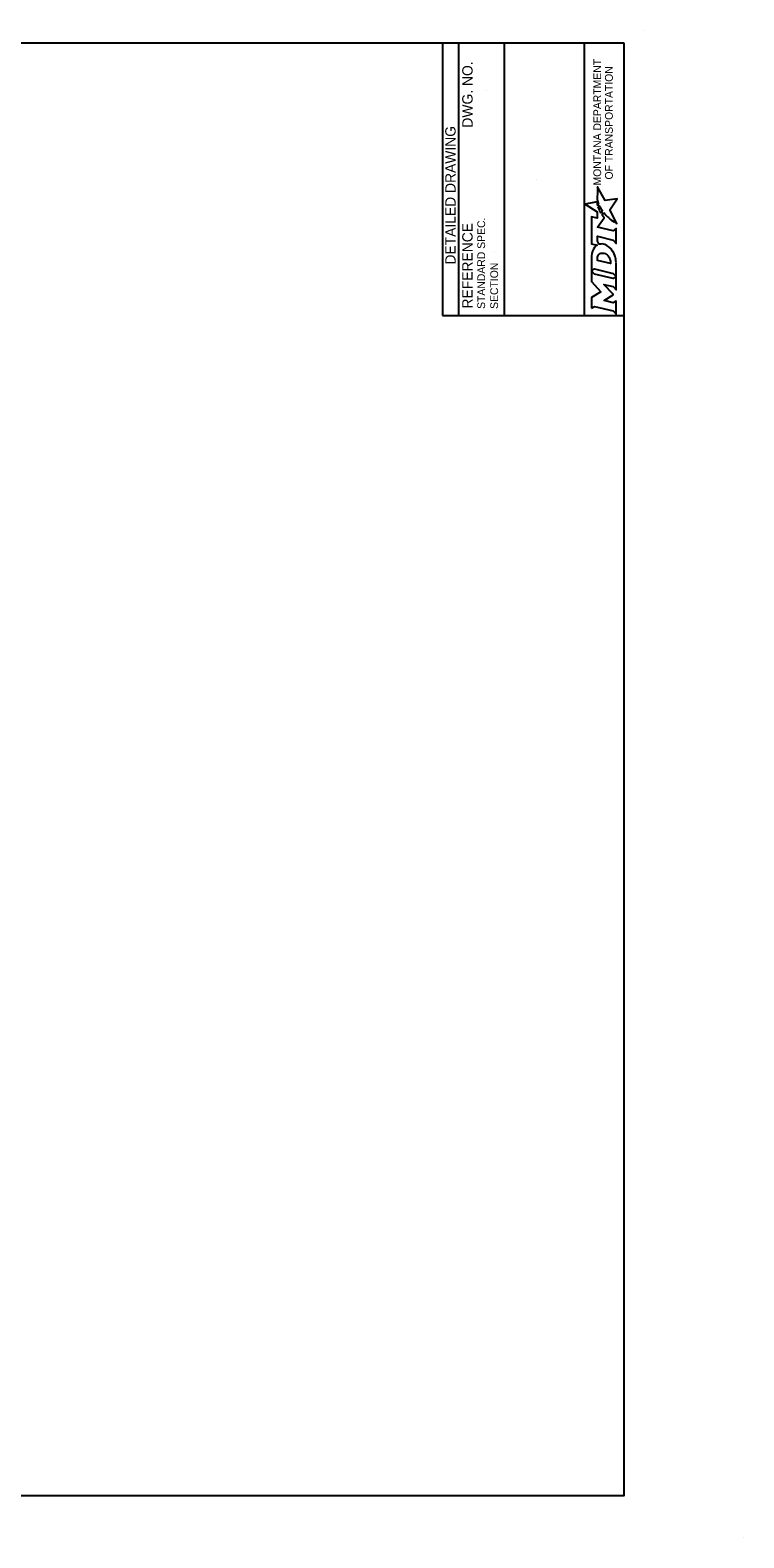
# Model space of a CAD drawing. Extents: x 49991.4 to 50048.3, y 49987.6 to 50018.3.
# Drawn here: x 50004.04 to 50009.54, y 49999.74 to 50011.36 of the extents above; entities that cross this region are included whole.
import ezdxf

# ---------------------------------------------------------------- set-up
doc = ezdxf.new("R2010")
doc.units = 0
doc.layers.add('Level 1', color=7, linetype='Continuous')
doc.layers.add('Level 3', color=7, linetype='Continuous')

msp = doc.modelspace()

# ---------------------------------------------------------------- linework, layer by layer
at = {"layer": 'Level 1'}
for p, q in [((50008.765, 50011.363), (50008.765, 50011.363)), ((50009.537, 49999.736), (50009.537, 49999.736))]:
    msp.add_line(p, q, dxfattribs=at)
msp.add_lwpolyline([(50008.615, 50011.263), (50000.336, 50011.263), (50000.336, 50000.062), (50008.615, 50000.062)], close=True, dxfattribs=at)
at = {"layer": 'Level 3'}
for p, q in [((50007.215, 50011.263), (50007.215, 50009.163)), ((50007.34, 50011.263), (50007.34, 50009.163)), ((50007.69, 50011.263), (50007.69, 50009.163)), ((50008.308, 50011.263), (50008.308, 50009.163)), ((50007.555, 50010.899), (50007.555, 50010.899)), ((50007.939, 50010.213), (50007.939, 50010.213)), ((50007.614, 50009.657), (50007.614, 50009.657)), ((50007.215, 50009.163), (50008.615, 50009.163))]:
    msp.add_line(p, q, dxfattribs=at)
for points in [[(50008.514, 50009.9), (50008.538, 50009.885), (50008.546, 50009.88), (50008.554, 50009.875), (50008.559, 50009.872), (50008.505, 50009.978), (50008.561, 50010.061), (50008.468, 50010.048), (50008.409, 50010.155), (50008.409, 50010.106), (50008.408, 50010.076), (50008.408, 50010.055), (50008.409, 50010.048), (50008.411, 50010.043), (50008.413, 50010.035), (50008.417, 50010.025)], [(50008.417, 50010.025), (50008.411, 50010.014), (50008.409, 50010.026), (50008.407, 50010.038), (50008.316, 50010.02), (50008.408, 50009.961), (50008.408, 50009.914), (50008.364, 50009.924), (50008.364, 50009.715), (50008.407, 50009.705), (50008.398, 50009.699)], [(50008.445, 50009.974), (50008.446, 50009.972), (50008.437, 50009.954), (50008.431, 50009.964), (50008.429, 50009.968), (50008.425, 50009.977), (50008.422, 50009.982), (50008.419, 50009.99), (50008.416, 50009.998), (50008.424, 50010.009), (50008.426, 50010.005), (50008.428, 50010.001), (50008.431, 50009.997), (50008.434, 50009.992), (50008.435, 50009.99), (50008.436, 50009.987), (50008.438, 50009.985), (50008.439, 50009.982), (50008.441, 50009.98), (50008.443, 50009.977), (50008.445, 50009.974)], [(50008.423, 50009.711), (50008.41, 50009.736), (50008.41, 50009.773), (50008.531, 50009.744), (50008.553, 50009.717), (50008.553, 50009.833), (50008.531, 50009.816), (50008.41, 50009.844), (50008.462, 50009.915), (50008.447, 50009.937), (50008.458, 50009.956)], [(50008.498, 50009.914), (50008.498, 50009.914)], [(50008.451, 50009.644), (50008.459, 50009.643), (50008.468, 50009.64), (50008.476, 50009.635), (50008.484, 50009.63), (50008.491, 50009.623), (50008.497, 50009.615), (50008.502, 50009.607), (50008.506, 50009.598), (50008.508, 50009.589), (50008.509, 50009.58), (50008.509, 50009.564), (50008.409, 50009.587), (50008.409, 50009.603), (50008.41, 50009.611), (50008.412, 50009.619), (50008.415, 50009.625), (50008.419, 50009.631), (50008.424, 50009.636), (50008.43, 50009.64), (50008.436, 50009.642), (50008.443, 50009.644), (50008.446, 50009.644), (50008.451, 50009.644)], [(50008.546, 50009.618), (50008.543, 50009.626), (50008.538, 50009.639), (50008.527, 50009.66)], [(50008.364, 50009.62), (50008.364, 50009.506), (50008.387, 50009.521), (50008.531, 50009.487), (50008.553, 50009.462), (50008.553, 50009.572)], [(50008.387, 50009.481), (50008.364, 50009.506), (50008.364, 50009.424), (50008.437, 50009.344), (50008.364, 50009.3), (50008.364, 50009.218)], [(50008.364, 50009.218), (50008.388, 50009.232), (50008.531, 50009.198), (50008.553, 50009.173), (50008.553, 50009.274), (50008.531, 50009.261), (50008.461, 50009.277), (50008.53, 50009.321), (50008.53, 50009.326), (50008.46, 50009.401), (50008.531, 50009.385), (50008.553, 50009.36), (50008.553, 50009.462), (50008.53, 50009.448), (50008.387, 50009.481)]]:
    msp.add_lwpolyline(points, dxfattribs=at)
for centre, radius, start, end in [((50008.443, 50009.643), 0.0709, 69.5329, 105.8582), ((50008.425, 50009.599), 0.118, 30.9103, 69.1383)]:
    msp.add_arc(centre, radius, start, end, dxfattribs=at)
for centre, major_axis, ratio, start_param, end_param in [((50008.468, 50009.945), (0.0097, -0.0112), 0.021651, 3.157348, 6.283185), ((50008.487, 50009.924), (0.0102, -0.0098), 0.016458, 3.141593, 6.279097), ((50008.506, 50009.907), (0.00806, -0.00694), 0.008222, 0, 3.137361), ((50008.412, 50009.618), (0.0037, 0.0834), 0.568097, 0.61298, 1.570796), ((50008.404, 50009.673), (0.0295, 0.0361), 0.469099, 1.225588, 1.570796), ((50008.405, 50009.573), (-0.148, 0), 0.987302, 3.139398, 3.456847)]:
    msp.add_ellipse(centre, major_axis=major_axis, ratio=ratio, start_param=start_param, end_param=end_param, dxfattribs=at)

# ---------------------------------------------------------------- texts
for s, height, p in [('DWG. NO.', 0.08, (50007.448, 50010.611)), ('MONTANA DEPARTMENT', 0.06, (50008.438, 50010.165)), ('OF TRANSPORTATION', 0.06, (50008.528, 50010.211)), ('DETAILED DRAWING', 0.0799, (50007.317, 50009.555)), ('REFERENCE', 0.08, (50007.448, 50009.216)), ('STANDARD SPEC.', 0.06, (50007.544, 50009.213)), ('SECTION', 0.06, (50007.644, 50009.213))]:
    msp.add_text(s, height=height, rotation=90, dxfattribs=at).set_placement(p)

doc.saveas('drawing.dxf')
